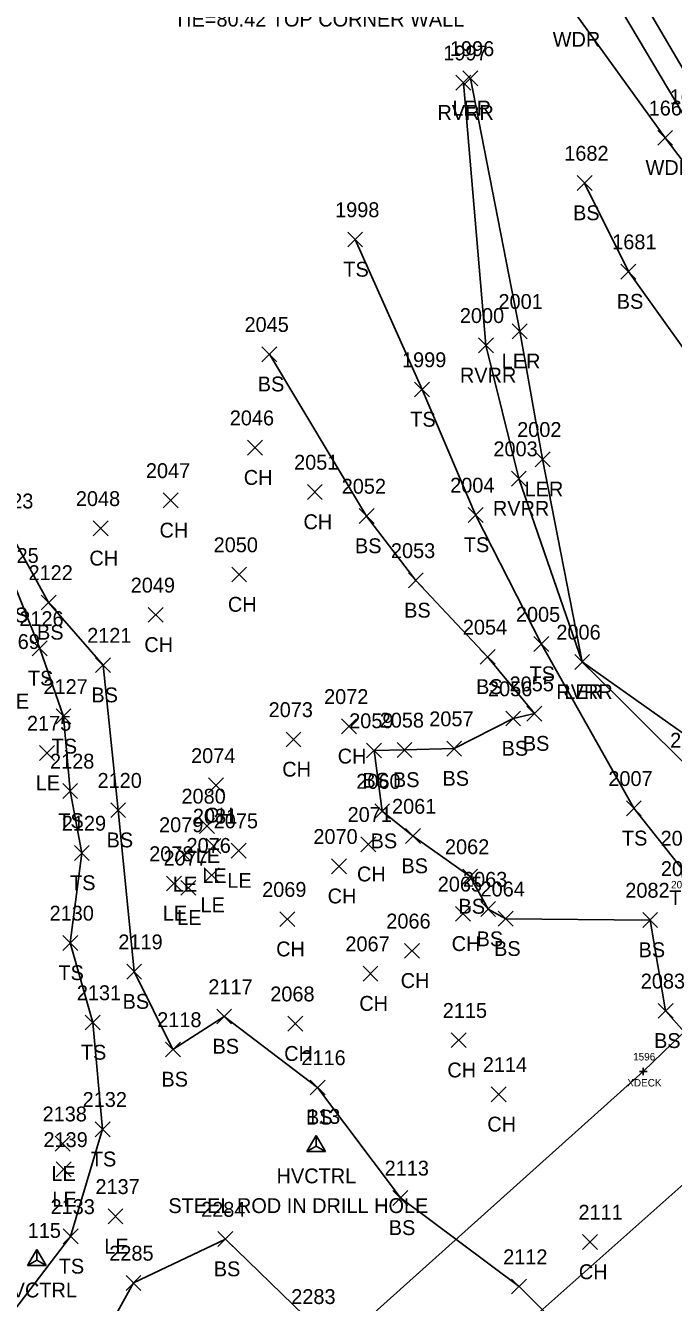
# Model space of a CAD drawing. Extents: x 1647133 to 1649138, y 411736 to 414924.
# Drawn here: x 1648877.6 to 1648964.6, y 412180 to 412351.7 of the extents above; entities that cross this region are included whole.
import ezdxf

# ---------------------------------------------------------------- set-up
doc = ezdxf.new("R2010")
doc.units = 0
for name, color, linetype in [('B_A', 7, 'Continuous'), ('B_I', 7, 'Continuous'), ('B_TIC', 7, 'Continuous'), ('BELB', 7, 'Continuous'), ('C_A', 7, 'Continuous'), ('C_C', 7, 'Continuous'), ('C_I', 7, 'Continuous'), ('CPSM', 7, 'Continuous'), ('L_A', 7, 'Continuous'), ('L_C', 7, 'Continuous'), ('L_I', 7, 'Continuous'), ('L_TIC', 7, 'Continuous'), ('LARO', 7, 'Continuous'), ('LAWA', 7, 'Continuous'), ('LAWE', 7, 'Continuous'), ('LELB', 7, 'Continuous')]:
    doc.layers.add(name, color=color, linetype=linetype)

msp = doc.modelspace()

# ---------------------------------------------------------------- linework, layer by layer
at = {"layer": 'B_TIC'}
msp.add_line((1648960.58, 412211.03), (1648960.66, 412211.03), dxfattribs=at)
for points in [[(1648960.08, 412211.03), (1648961.08, 412211.03)], [(1648960.58, 412210.53), (1648960.58, 412211.53)]]:
    msp.add_lwpolyline(points, dxfattribs=at)
at = {"layer": 'BELB'}
for points in [[(1648856.37, 412097.64), (1648845.78, 412109.6), (1648891.84, 412149.62), (1648923.12, 412177.42), (1648960.58, 412211.03), (1648974.89, 412224.91)], [(1648856.37, 412097.64), (1648904.08, 412141.16), (1648932.96, 412166.56), (1648970.05, 412199.52), (1648985.33, 412212.82), (1648974.89, 412224.91)]]:
    msp.add_lwpolyline(points, dxfattribs=at)
at = {"layer": 'CPSM'}
for p, q in [((1648915.37, 412200.29), (1648916.62, 412202.45)), ((1648917.87, 412200.29), (1648916.62, 412202.45)), ((1648916.62, 412201.01), (1648916.62, 412202.45)), ((1648915.37, 412200.29), (1648916.62, 412201.01)), ((1648916.62, 412201.01), (1648916.62, 412201.01)), ((1648916.62, 412201.01), (1648917.87, 412200.29)), ((1648915.37, 412200.29), (1648917.87, 412200.29)), ((1648877.85, 412184.95), (1648879.1, 412187.11)), ((1648880.35, 412184.95), (1648879.1, 412187.11)), ((1648879.1, 412185.67), (1648879.1, 412187.11)), ((1648877.85, 412184.95), (1648879.1, 412185.67)), ((1648879.1, 412185.67), (1648879.1, 412185.67)), ((1648879.1, 412185.67), (1648880.35, 412184.95)), ((1648877.85, 412184.95), (1648880.35, 412184.95))]:
    msp.add_line(p, q, dxfattribs=at)
at = {"layer": 'L_TIC'}
for points in [[(1648935.41, 412342.99), (1648937.41, 412344.99)], [(1648937.41, 412342.99), (1648935.41, 412344.99)], [(1648936.35, 412343.57), (1648938.35, 412345.57)], [(1648938.35, 412343.57), (1648936.35, 412345.57)], [(1648962.52, 412335.58), (1648964.52, 412337.58)], [(1648964.52, 412335.58), (1648962.52, 412337.58)], [(1648951.7, 412329.5), (1648953.7, 412331.5)], [(1648953.7, 412329.5), (1648951.7, 412331.5)], [(1648920.87, 412321.91), (1648922.87, 412323.91)], [(1648922.87, 412321.91), (1648920.87, 412323.91)], [(1648957.57, 412317.59), (1648959.57, 412319.59)], [(1648959.57, 412317.59), (1648957.57, 412319.59)], [(1648942.97, 412309.57), (1648944.97, 412311.57)], [(1648944.97, 412309.57), (1648942.97, 412311.57)], [(1648938.43, 412307.68), (1648940.43, 412309.68)], [(1648940.43, 412307.68), (1648938.43, 412309.68)], [(1648909.34, 412306.48), (1648911.34, 412308.48)], [(1648911.34, 412306.48), (1648909.34, 412308.48)], [(1648929.86, 412301.74), (1648931.86, 412303.74)], [(1648931.86, 412301.74), (1648929.86, 412303.74)], [(1648907.41, 412293.92), (1648909.41, 412295.92)], [(1648909.41, 412293.92), (1648907.41, 412295.92)], [(1648946.05, 412292.36), (1648948.05, 412294.36)], [(1648948.05, 412292.36), (1648946.05, 412294.36)], [(1648942.85, 412289.76), (1648944.85, 412291.76)], [(1648944.85, 412289.76), (1648942.85, 412291.76)], [(1648896.09, 412286.83), (1648898.09, 412288.83)], [(1648898.09, 412286.83), (1648896.09, 412288.83)], [(1648915.44, 412287.96), (1648917.44, 412289.96)], [(1648917.44, 412287.96), (1648915.44, 412289.96)], [(1648922.4, 412284.73), (1648924.4, 412286.73)], [(1648924.4, 412284.73), (1648922.4, 412286.73)], [(1648937.05, 412284.87), (1648939.05, 412286.87)], [(1648939.05, 412284.87), (1648937.05, 412286.87)], [(1648886.68, 412283.07), (1648888.68, 412285.07)], [(1648888.68, 412283.07), (1648886.68, 412285.07)], [(1648905.28, 412276.86), (1648907.28, 412278.86)], [(1648907.28, 412276.86), (1648905.28, 412278.86)], [(1648929.01, 412276.07), (1648931.01, 412278.07)], [(1648931.01, 412276.07), (1648929.01, 412278.07)], [(1648879.68, 412273.11), (1648881.68, 412275.11)], [(1648881.68, 412273.11), (1648879.68, 412275.11)], [(1648894.05, 412271.44), (1648896.05, 412273.44)], [(1648896.05, 412271.44), (1648894.05, 412273.44)], [(1648945.88, 412267.51), (1648947.88, 412269.51)], [(1648947.88, 412267.51), (1648945.88, 412269.51)], [(1648878.49, 412266.93), (1648880.49, 412268.93)], [(1648880.49, 412266.93), (1648878.49, 412268.93)], [(1648938.66, 412265.79), (1648940.66, 412267.79)], [(1648940.66, 412265.79), (1648938.66, 412267.79)], [(1648886.99, 412264.68), (1648888.99, 412266.68)], [(1648888.99, 412264.68), (1648886.99, 412266.68)], [(1648951.37, 412265.11), (1648953.37, 412267.11)], [(1648953.37, 412265.11), (1648951.37, 412267.11)], [(1648951.37, 412265.11), (1648953.37, 412267.11)], [(1648953.37, 412265.11), (1648951.37, 412267.11)], [(1648881.68, 412257.79), (1648883.68, 412259.79)], [(1648883.68, 412257.79), (1648881.68, 412259.79)], [(1648942.1, 412257.5), (1648944.1, 412259.5)], [(1648944.1, 412257.5), (1648942.1, 412259.5)], [(1648944.95, 412258.16), (1648946.95, 412260.16)], [(1648946.95, 412258.16), (1648944.95, 412260.16)], [(1648920.03, 412256.45), (1648922.03, 412258.45)], [(1648922.03, 412256.45), (1648920.03, 412258.45)], [(1648912.58, 412254.69), (1648914.58, 412256.69)], [(1648914.58, 412254.69), (1648912.58, 412256.69)], [(1648879.47, 412252.86), (1648881.47, 412254.86)], [(1648881.47, 412252.86), (1648879.47, 412254.86)], [(1648923.41, 412253.2), (1648925.41, 412255.2)], [(1648925.41, 412253.2), (1648923.41, 412255.2)], [(1648927.5, 412253.28), (1648929.5, 412255.28)], [(1648929.5, 412253.28), (1648927.5, 412255.28)], [(1648934.16, 412253.46), (1648936.16, 412255.46)], [(1648936.16, 412253.46), (1648934.16, 412255.46)], [(1648902.16, 412248.51), (1648904.16, 412250.51)], [(1648904.16, 412248.51), (1648902.16, 412250.51)], [(1648882.57, 412247.77), (1648884.57, 412249.77)], [(1648884.57, 412247.77), (1648882.57, 412249.77)], [(1648889.03, 412245.18), (1648891.03, 412247.18)], [(1648891.03, 412245.18), (1648889.03, 412247.18)], [(1648958.3, 412245.43), (1648960.3, 412247.43)], [(1648960.3, 412245.43), (1648958.3, 412247.43)], [(1648924.5, 412245.05), (1648926.5, 412247.05)], [(1648926.5, 412245.05), (1648924.5, 412247.05)], [(1648900.96, 412243.06), (1648902.96, 412245.06)], [(1648902.96, 412243.06), (1648900.96, 412245.06)], [(1648928.64, 412241.7), (1648930.64, 412243.7)], [(1648930.64, 412241.7), (1648928.64, 412243.7)], [(1648901.83, 412240.37), (1648903.83, 412242.37)], [(1648903.83, 412240.37), (1648901.83, 412242.37)], [(1648922.63, 412240.6), (1648924.63, 412242.6)], [(1648924.63, 412240.6), (1648922.63, 412242.6)], [(1648884.15, 412239.42), (1648886.15, 412241.42)], [(1648886.15, 412239.42), (1648884.15, 412241.42)], [(1648897.87, 412239.22), (1648899.87, 412241.22)], [(1648899.87, 412239.22), (1648897.87, 412241.22)], [(1648905.2, 412239.74), (1648907.2, 412241.74)], [(1648907.2, 412239.74), (1648905.2, 412241.74)], [(1648918.68, 412237.64), (1648920.68, 412239.64)], [(1648920.68, 412237.64), (1648918.68, 412239.64)], [(1648896.53, 412235.32), (1648898.53, 412237.32)], [(1648898.53, 412235.32), (1648896.53, 412237.32)], [(1648901.6, 412236.44), (1648903.6, 412238.44)], [(1648903.6, 412236.44), (1648901.6, 412238.44)], [(1648936.31, 412236.26), (1648938.31, 412238.26)], [(1648938.31, 412236.26), (1648936.31, 412238.26)], [(1648898.46, 412234.74), (1648900.46, 412236.74)], [(1648900.46, 412234.74), (1648898.46, 412236.74)], [(1648938.74, 412231.88), (1648940.74, 412233.88)], [(1648940.74, 412231.88), (1648938.74, 412233.88)], [(1648911.76, 412230.52), (1648913.76, 412232.52)], [(1648913.76, 412230.52), (1648911.76, 412232.52)], [(1648935.34, 412231.24), (1648937.34, 412233.24)], [(1648937.34, 412231.24), (1648935.34, 412233.24)], [(1648941.09, 412230.58), (1648943.09, 412232.58)], [(1648943.09, 412230.58), (1648941.09, 412232.58)], [(1648960.5, 412230.41), (1648962.5, 412232.41)], [(1648962.5, 412230.41), (1648960.5, 412232.41)], [(1648882.59, 412227.33), (1648884.59, 412229.33)], [(1648884.59, 412227.33), (1648882.59, 412229.33)], [(1648928.49, 412226.27), (1648930.49, 412228.27)], [(1648930.49, 412226.27), (1648928.49, 412228.27)], [(1648891.18, 412223.47), (1648893.18, 412225.47)], [(1648893.18, 412223.47), (1648891.18, 412225.47)], [(1648922.93, 412223.2), (1648924.93, 412225.2)], [(1648924.93, 412223.2), (1648922.93, 412225.2)], [(1648962.58, 412218.2), (1648964.58, 412220.2)], [(1648964.58, 412218.2), (1648962.58, 412220.2)], [(1648885.6, 412216.63), (1648887.6, 412218.63)], [(1648887.6, 412216.63), (1648885.6, 412218.63)], [(1648903.26, 412217.44), (1648905.26, 412219.44)], [(1648905.26, 412217.44), (1648903.26, 412219.44)], [(1648912.84, 412216.47), (1648914.84, 412218.47)], [(1648914.84, 412216.47), (1648912.84, 412218.47)], [(1648934.76, 412214.25), (1648936.76, 412216.25)], [(1648936.76, 412214.25), (1648934.76, 412216.25)], [(1648896.39, 412213.01), (1648898.39, 412215.01)], [(1648898.39, 412213.01), (1648896.39, 412215.01)], [(1648915.82, 412207.9), (1648917.82, 412209.9)], [(1648917.82, 412207.9), (1648915.82, 412209.9)], [(1648940.14, 412206.97), (1648942.14, 412208.97)], [(1648942.14, 412206.97), (1648940.14, 412208.97)], [(1648886.94, 412202.28), (1648888.94, 412204.28)], [(1648888.94, 412202.28), (1648886.94, 412204.28)], [(1648881.56, 412200.33), (1648883.56, 412202.33)], [(1648883.56, 412200.33), (1648881.56, 412202.33)], [(1648881.69, 412196.88), (1648883.69, 412198.88)], [(1648883.69, 412196.88), (1648881.69, 412198.88)], [(1648926.94, 412193.05), (1648928.94, 412195.05)], [(1648928.94, 412193.05), (1648926.94, 412195.05)], [(1648888.67, 412190.57), (1648890.67, 412192.57)], [(1648890.67, 412190.57), (1648888.67, 412192.57)], [(1648882.63, 412187.87), (1648884.63, 412189.87)], [(1648884.63, 412187.87), (1648882.63, 412189.87)], [(1648903.43, 412187.51), (1648905.43, 412189.51)], [(1648905.43, 412187.51), (1648903.43, 412189.51)], [(1648952.43, 412187.12), (1648954.43, 412189.12)], [(1648954.43, 412187.12), (1648952.43, 412189.12)], [(1648891.09, 412181.61), (1648893.09, 412183.61)], [(1648893.09, 412181.61), (1648891.09, 412183.61)], [(1648942.88, 412181.13), (1648944.88, 412183.13)], [(1648944.88, 412181.13), (1648942.88, 412183.13)]]:
    msp.add_lwpolyline(points, dxfattribs=at)
at = {"layer": 'LARO'}
msp.add_lwpolyline([(1648937.35, 412344.57), (1648943.97, 412310.57), (1648947.05, 412293.36), (1648952.37, 412266.11), (1648967.01, 412251.58)], dxfattribs=at)
at = {"layer": 'LAWA'}
msp.add_lwpolyline([(1648951.05, 412353.82), (1648963.52, 412336.58), (1648974.71, 412321.82), (1648986.89, 412301.75), (1648993.21, 412292.05), (1648994.54, 412281.3), (1648991.32, 412266.13), (1648987.65, 412250.05), (1648975.93, 412241.95)], dxfattribs=at)
at = {"layer": 'LAWE'}
msp.add_lwpolyline([(1648936.41, 412343.99), (1648939.43, 412308.68), (1648943.85, 412290.76), (1648952.37, 412266.11), (1648968.93, 412254.38)], dxfattribs=at)
at = {"layer": 'LELB'}
for points in [[(1648958.6, 412358.35), (1648969.4, 412339.95), (1648979.6, 412320.41), (1648988.67, 412309.59), (1648996.92, 412293.43), (1648997.15, 412280.66), (1648991.32, 412266.13)], [(1648955.83, 412356.84), (1648966.91, 412338.1), (1648974.71, 412321.82)], [(1648975.7, 412250.53), (1648977.59, 412262.81), (1648981.91, 412271.44), (1648983.35, 412278.25), (1648982.24, 412288), (1648969.91, 412302.76), (1648958.57, 412318.59), (1648952.7, 412330.5)], [(1648921.87, 412322.91), (1648930.86, 412302.74), (1648938.05, 412285.87), (1648946.88, 412268.51), (1648959.3, 412246.43), (1648965.67, 412238.41), (1648966.29, 412234.32)], [(1648910.34, 412307.48), (1648923.4, 412285.73), (1648930.01, 412277.07), (1648939.66, 412266.79), (1648945.95, 412259.16), (1648943.1, 412258.5), (1648935.16, 412254.46), (1648928.5, 412254.28), (1648924.41, 412254.2), (1648925.5, 412246.05), (1648929.64, 412242.7), (1648937.31, 412237.26), (1648939.74, 412232.88), (1648942.09, 412231.58), (1648961.5, 412231.41), (1648963.58, 412219.2), (1648985.51, 412194.57), (1648993.76, 412177.98), (1649005.16, 412156.05), (1649014.95, 412138.53), (1649020.66, 412120.02), (1649027.35, 412106.95), (1649037.64, 412094.49)], [(1648988.62, 412076.26), (1648991.76, 412087.72), (1648981.69, 412120.13), (1648975.99, 412150.04), (1648943.88, 412182.13), (1648927.94, 412194.05), (1648916.82, 412208.9), (1648904.26, 412218.44), (1648897.39, 412214.01), (1648892.18, 412224.47), (1648890.03, 412246.18), (1648887.99, 412265.68), (1648880.68, 412274.11), (1648875.37, 412283.75)], [(1648866.33, 412278.88), (1648876.09, 412276.42), (1648879.49, 412267.93), (1648882.68, 412258.79), (1648883.57, 412248.77), (1648885.15, 412240.42), (1648883.59, 412228.33), (1648886.6, 412217.63), (1648887.94, 412203.28), (1648883.63, 412188.87), (1648865.63, 412165.29), (1648858.29, 412164.92), (1648847.42, 412160.58)], [(1648974.71, 412106.25), (1648962.14, 412130.24), (1648924.84, 412165.77), (1648916.54, 412176.78), (1648904.43, 412188.51), (1648892.09, 412182.61), (1648887.59, 412174.51), (1648883, 412162.55)]]:
    msp.add_lwpolyline(points, dxfattribs=at)

# ---------------------------------------------------------------- texts
at = {"layer": 'B_A'}
msp.add_text('XDECK', height=1, dxfattribs=at).set_placement((1648958.42, 412209.03))
at = {"layer": 'B_I'}
for s, p in [('2030', (1648964.31, 412235.67)), ('1596', (1648959.21, 412212.53))]:
    msp.add_text(s, height=1, dxfattribs=at).set_placement(p)
at = {"layer": 'C_A'}
for p in [(1648911.31, 412196.01), (1648873.79, 412180.67)]:
    msp.add_text('HVCTRL', height=2, dxfattribs=at).set_placement(p)
at = {"layer": 'C_C'}
msp.add_text('STEEL ROD IN DRILL HOLE', height=2, dxfattribs=at).set_placement((1648896.77, 412192.01))
at = {"layer": 'C_I'}
for s, p in [('113', (1648915.39, 412204.01)), ('115', (1648877.87, 412188.67))]:
    msp.add_text(s, height=2, dxfattribs=at).set_placement(p)
at = {"layer": 'L_A'}
for s, p in [('WDR', (1648948.41, 412348.82)), ('LER', (1648934.93, 412339.57)), ('RVRR', (1648932.92, 412338.99)), ('WDR', (1648960.88, 412331.58)), ('BS', (1648951.14, 412325.5)), ('TS', (1648920.28, 412317.91)), ('BS', (1648957.01, 412313.59)), ('LER', (1648941.55, 412305.57)), ('RVRR', (1648935.94, 412303.68)), ('BS', (1648908.78, 412302.48)), ('TS', (1648929.27, 412297.74)), ('CH', (1648906.9, 412289.92)), ('LER', (1648944.63, 412288.36)), ('RVRR', (1648940.37, 412285.76)), ('CH', (1648895.58, 412282.83)), ('CH', (1648914.92, 412283.96)), ('BS', (1648921.84, 412280.73)), ('TS', (1648936.46, 412280.87)), ('CH', (1648886.16, 412279.07)), ('CH', (1648904.77, 412272.86)), ('TS', (1648874.5, 412271.42)), ('BS', (1648928.45, 412272.07)), ('BS', (1648879.12, 412269.11)), ('CH', (1648893.54, 412267.44)), ('TS', (1648877.9, 412262.93)), ('TS', (1648945.29, 412263.51)), ('BS', (1648886.43, 412260.68)), ('BS', (1648938.11, 412261.79)), ('RVRR', (1648948.89, 412261.11)), ('LER', (1648949.96, 412261.11)), ('LE', (1648874.79, 412259.85)), ('TS', (1648881.09, 412253.79)), ('BS', (1648944.39, 412254.16)), ('CH', (1648919.52, 412252.45)), ('BS', (1648941.54, 412253.5)), ('CH', (1648912.07, 412250.69)), ('LE', (1648878.95, 412248.86)), ('BS', (1648922.85, 412249.2)), ('BS', (1648926.94, 412249.28)), ('BS', (1648933.6, 412249.46)), ('TS', (1648881.98, 412243.77)), ('CH', (1648901.64, 412244.51)), ('BS', (1648888.47, 412241.18)), ('BS', (1648923.94, 412241.05)), ('TS', (1648957.71, 412241.43)), ('LE', (1648900.45, 412239.06)), ('CH', (1648922.11, 412236.6)), ('BS', (1648928.08, 412237.7)), ('TS', (1648883.56, 412235.42)), ('LE', (1648897.36, 412235.22)), ('LE', (1648901.32, 412236.37)), ('LE', (1648904.69, 412235.74)), ('CH', (1648918.17, 412233.64)), ('TS', (1648964.08, 412233.41)), ('LE', (1648901.09, 412232.44)), ('BS', (1648935.75, 412232.26)), ('LE', (1648896.02, 412231.32)), ('LE', (1648897.95, 412230.74)), ('BS', (1648938.18, 412227.88)), ('CH', (1648911.25, 412226.52)), ('CH', (1648934.83, 412227.24)), ('BS', (1648940.53, 412226.58)), ('BS', (1648959.94, 412226.41)), ('TS', (1648882, 412223.33)), ('CH', (1648927.98, 412222.27)), ('BS', (1648890.62, 412219.47)), ('CH', (1648922.42, 412219.2)), ('BS', (1648962.02, 412214.2)), ('TS', (1648885.01, 412212.63)), ('BS', (1648902.7, 412213.44)), ('CH', (1648912.33, 412212.47)), ('BS', (1648895.84, 412209.01)), ('CH', (1648934.25, 412210.25)), ('BS', (1648915.26, 412203.9)), ('CH', (1648939.62, 412202.97)), ('TS', (1648886.35, 412198.28)), ('LE', (1648881.05, 412196.33)), ('LE', (1648881.18, 412192.88)), ('BS', (1648926.38, 412189.05)), ('LE', (1648888.16, 412186.57)), ('TS', (1648882.04, 412183.87)), ('BS', (1648902.87, 412183.51)), ('CH', (1648951.92, 412183.12))]:
    msp.add_text(s, height=2, dxfattribs=at).set_placement(p)
at = {"layer": 'L_C'}
msp.add_text('TIE=80.42 TOP CORNER WALL', height=2, dxfattribs=at).set_placement((1648897.51, 412351.54))
at = {"layer": 'L_I'}
for s, p in [('1997', (1648933.71, 412346.99)), ('1996', (1648934.6, 412347.57)), ('1661', (1648961.3, 412339.58)), ('1662', (1648964.12, 412341.1)), ('1682', (1648949.96, 412333.5)), ('1998', (1648919.17, 412325.91)), ('1681', (1648956.4, 412321.59)), ('2001', (1648941.12, 412313.57)), ('2045', (1648907, 412310.48)), ('2000', (1648935.93, 412311.68)), ('1999', (1648928.16, 412305.74)), ('2046', (1648905.02, 412297.92)), ('2002', (1648943.63, 412296.36)), ('2003', (1648940.44, 412293.76)), ('2051', (1648913.66, 412291.96)), ('2047', (1648893.75, 412290.83)), ('2052', (1648920.06, 412288.73)), ('2004', (1648934.63, 412288.87)), ('2123', (1648872.68, 412286.75)), ('2048', (1648884.34, 412287.07)), ('2125', (1648873.4, 412279.42)), ('2050', (1648902.85, 412280.86)), ('2053', (1648926.67, 412280.07)), ('2122', (1648877.98, 412277.11)), ('2049', (1648891.71, 412275.44)), ('2126', (1648876.74, 412270.93)), ('2005', (1648943.46, 412271.51)), ('2054', (1648936.33, 412269.79)), ('2006', (1648948.9, 412269.11)), ('2006', (1648948.9, 412269.11)), ('2169', (1648873.55, 412267.85)), ('2121', (1648885.86, 412268.68)), ('2127', (1648879.99, 412261.79)), ('2056', (1648939.71, 412261.5)), ('2055', (1648942.61, 412262.16)), ('2072', (1648917.69, 412260.45)), ('2073', (1648910.24, 412258.69)), ('2059', (1648921.06, 412257.2)), ('2058', (1648925.16, 412257.28)), ('2057', (1648931.82, 412257.46)), ('2175', (1648877.77, 412256.86)), ('2016', (1648964.18, 412254.58)), ('2074', (1648899.82, 412252.51)), ('2128', (1648880.87, 412251.77)), ('2120', (1648887.25, 412249.18)), ('2060', (1648922.02, 412249.05)), ('2007', (1648955.88, 412249.43)), ('2080', (1648898.53, 412247.06)), ('2061', (1648926.82, 412245.7)), ('2129', (1648882.45, 412243.42)), ('2081', (1648900.06, 412244.37)), ('2075', (1648902.86, 412243.74)), ('2071', (1648920.85, 412244.6)), ('2079', (1648895.52, 412243.22)), ('2070', (1648916.25, 412241.64)), ('2076', (1648899.21, 412240.44)), ('2062', (1648933.93, 412240.26)), ('2017', (1648962.9, 412241.41)), ('2078', (1648894.19, 412239.32)), ('2077', (1648896.12, 412238.74)), ('2029', (1648962.94, 412237.32)), ('2065', (1648932.96, 412235.24)), ('2063', (1648936.35, 412235.88)), ('2069', (1648909.37, 412234.52)), ('2064', (1648938.71, 412234.58)), ('2082', (1648958.16, 412234.41)), ('2130', (1648880.81, 412231.33)), ('2066', (1648926.05, 412230.27)), ('2119', (1648890.05, 412227.47)), ('2067', (1648920.55, 412227.2)), ('2117', (1648902.14, 412221.44)), ('2083', (1648960.24, 412222.2)), ('2131', (1648884.47, 412220.63)), ('2068', (1648910.46, 412220.47)), ('2115', (1648933.63, 412218.25)), ('2118', (1648895.27, 412217.01)), ('2116', (1648914.64, 412211.9)), ('2114', (1648939.01, 412210.97)), ('2132', (1648885.25, 412206.28)), ('2138', (1648879.87, 412204.33)), ('2139', (1648879.99, 412200.88)), ('2113', (1648925.82, 412197.05)), ('2137', (1648886.97, 412194.57)), ('2133', (1648880.94, 412191.87)), ('2284', (1648901.17, 412191.51)), ('2111', (1648951.87, 412191.12)), ('2285', (1648888.83, 412185.61)), ('2112', (1648941.75, 412185.13)), ('2283', (1648913.28, 412179.78))]:
    msp.add_text(s, height=2, dxfattribs=at).set_placement(p)

doc.saveas('drawing.dxf')
